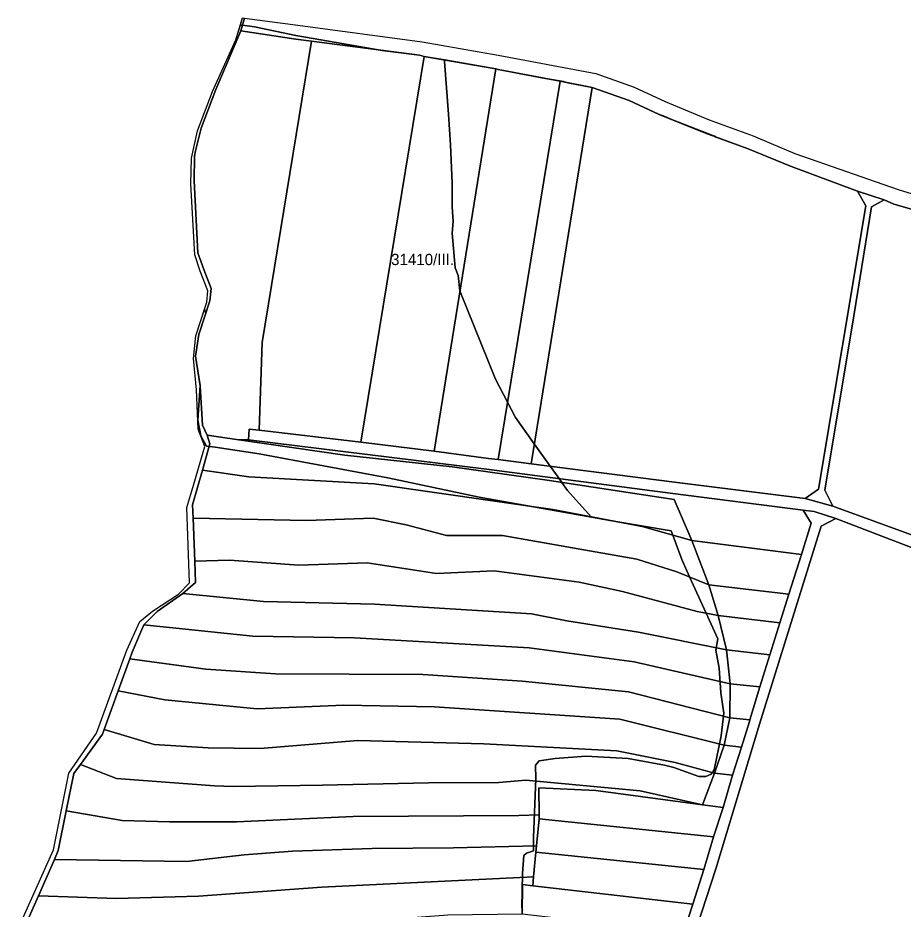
# Model space of a CAD drawing. Extents: x -541351 to -537540, y -1162694 to -1159725.
# Drawn here: x -540770.9 to -540378.9, y -1160119.8 to -1159725 of the extents above; entities that cross this region are included whole.
import ezdxf

# ---------------------------------------------------------------- set-up
doc = ezdxf.new("R2010")
doc.units = 0
for name, color, linetype in [('95560013', 7, 'Continuous'), ('95590013', 7, 'Continuous'), ('95610013', 7, 'Continuous'), ('95620013', 7, 'Continuous'), ('95630013', 7, 'Continuous'), ('95640013', 7, 'Continuous'), ('95660013', 7, 'Continuous')]:
    doc.layers.add(name, color=color, linetype=linetype)

msp = doc.modelspace()

# ---------------------------------------------------------------- linework, layer by layer
at = {"layer": '95560013'}
for points in [[(-540687.01, -1159909.85), (-540689.14, -1159905.33), (-540690.2, -1159888.02), (-540692.23, -1159874.8), (-540690.71, -1159865.31), (-540685.82, -1159850.31), (-540685.23, -1159844.82), (-540688.53, -1159836.42), (-540691.19, -1159829.1), (-540692.84, -1159797.23), (-540692.6, -1159786.19), (-540692.25, -1159783.95), (-540689.66, -1159773.88), (-540683.29, -1159756.73), (-540672.18, -1159730.75), (-540647.86, -1159734.45), (-540640.92, -1159735.38), (-540662.69, -1159868.81), (-540664.02, -1159907.64), (-540668.5, -1159907.14), (-540668.76, -1159911.89), (-540672.98, -1159911.96)], [(-540662.69, -1159868.81), (-540640.92, -1159735.38), (-540593.02, -1159741.59), (-540590.97, -1159742.06), (-540618.99, -1159912.95), (-540664.02, -1159907.64)], [(-540559.26, -1159747.62), (-540586.55, -1159916.94), (-540618.99, -1159912.95), (-540590.97, -1159742.06)], [(-540558.18, -1159920.55), (-540562.46, -1159920.09), (-540586.55, -1159916.94), (-540559.26, -1159747.62), (-540558.18, -1159747.82), (-540530.77, -1159753.07)], [(-540558.18, -1159920.55), (-540530.77, -1159753.07), (-540516.55, -1159755.86), (-540543.65, -1159922.47)], [(-540500.27, -1159761.58), (-540486.88, -1159767.77), (-540466.37, -1159776.14), (-540447.5, -1159783.05), (-540428.8, -1159790.68), (-540399.07, -1159801.69), (-540395.39, -1159808.26), (-540416.42, -1159933.74), (-540422.33, -1159937.95), (-540481.31, -1159930.52), (-540543.65, -1159922.47), (-540516.55, -1159755.86)], [(-540392.94, -1159808.75), (-540387.33, -1159805.56), (-540383.07, -1159807.44), (-540355.38, -1159815.32), (-540315.69, -1159826.05), (-540281.01, -1159835.88), (-540330.36, -1159970.74), (-540352.96, -1159962.05), (-540409.96, -1159941.32), (-540413.54, -1159934.22), (-540400.75, -1159856.93)], [(-540356.83, -1160306.42), (-540508.48, -1160249.81), (-540502.49, -1160230.24), (-540493.25, -1160200.09), (-540483.27, -1160166.95), (-540480.24, -1160158.64), (-540461.87, -1160101.94), (-540442.45, -1160037.81), (-540415.15, -1159950.06), (-540408.75, -1159946.72), (-540359.07, -1159965.85), (-540332.08, -1159975.44), (-540333.53, -1159979.4), (-540310.02, -1160032.13), (-540317.01, -1160072.74), (-540332.5, -1160163.53), (-540349.68, -1160266.25)]]:
    msp.add_lwpolyline(points, close=True, dxfattribs=at)
at = {"layer": '95590013'}
for points in [[(-540672.98, -1159911.96), (-540668.76, -1159911.89), (-540563.34, -1159924.9), (-540480.83, -1159935.64), (-540423.17, -1159943.05), (-540419.69, -1159948.79), (-540423.93, -1159962.65), (-540472.52, -1159956.54), (-540480.23, -1159938.25), (-540536.53, -1159929.78), (-540578.61, -1159923.89), (-540626.15, -1159918.63)], [(-540429.55, -1159980.28), (-540464.95, -1159976.07), (-540472.52, -1159956.54), (-540423.93, -1159962.65)]]:
    msp.add_lwpolyline(points, close=True, dxfattribs=at)
at = {"layer": '95610013'}
for points in [[(-540416.42, -1159933.74), (-540395.39, -1159808.26), (-540399.07, -1159801.69), (-540387.33, -1159805.56), (-540392.94, -1159808.75), (-540400.75, -1159856.93), (-540413.54, -1159934.22), (-540409.96, -1159941.32), (-540422.33, -1159937.95)], [(-540467.2, -1160102.19), (-540541.49, -1160094.53), (-540541.2, -1160091.66), (-540540.01, -1160079.71), (-540462.81, -1160087.74), (-540466.74, -1160100.71)], [(-540542.51, -1160105.39), (-540541.49, -1160094.53), (-540467.2, -1160102.19), (-540472.02, -1160117.6), (-540542.89, -1160109.37)], [(-540472.02, -1160117.6), (-540476.19, -1160130.2), (-540547.6, -1160121.95), (-540547.45, -1160108.79), (-540542.89, -1160109.37)]]:
    msp.add_lwpolyline(points, close=True, dxfattribs=at)
at = {"layer": '95620013'}
for points in [[(-540536.53, -1159929.78), (-540480.23, -1159938.25), (-540472.52, -1159956.54), (-540494.39, -1159950.23), (-540534.02, -1159942.82), (-540613.05, -1159931.36), (-540668.68, -1159928.25), (-540689.1, -1159925.28), (-540685.86, -1159913.66), (-540687.01, -1159909.85), (-540672.98, -1159911.96), (-540626.15, -1159918.63), (-540578.61, -1159923.89)], [(-540693.27, -1159946.58), (-540693.48, -1159940.71), (-540689.1, -1159925.28), (-540668.68, -1159928.25), (-540613.05, -1159931.36), (-540534.02, -1159942.82), (-540494.39, -1159950.23), (-540472.52, -1159956.54), (-540464.95, -1159976.07), (-540479.17, -1159970.29), (-540496.78, -1159964.81), (-540556.23, -1159954.29), (-540581.06, -1159954.29), (-540598.9, -1159949.56), (-540613.53, -1159946.65), (-540643.03, -1159947.58)], [(-540616.21, -1159966.36), (-540646.47, -1159967.48), (-540677.1, -1159965.24), (-540692.59, -1159965.67), (-540693.27, -1159946.58), (-540643.03, -1159947.58), (-540613.53, -1159946.65), (-540598.9, -1159949.56), (-540581.06, -1159954.29), (-540556.23, -1159954.29), (-540496.78, -1159964.81), (-540479.17, -1159970.29), (-540464.95, -1159976.07), (-540460.86, -1159989.73), (-540470.08, -1159987.93), (-540503.12, -1159979.1), (-540522.36, -1159974.98), (-540559.91, -1159969.94), (-540585.58, -1159971.03)], [(-540496.05, -1159997.14), (-540527.86, -1159992), (-540543.42, -1159988.94), (-540612.9, -1159984.64), (-540662.17, -1159983.52), (-540697.84, -1159979.97), (-540692.26, -1159975.02), (-540692.59, -1159965.67), (-540677.1, -1159965.24), (-540646.47, -1159967.48), (-540616.21, -1159966.36), (-540585.58, -1159971.03), (-540559.91, -1159969.94), (-540522.36, -1159974.98), (-540503.12, -1159979.1), (-540470.08, -1159987.93), (-540460.86, -1159989.73), (-540457.12, -1160004.92)], [(-540433.56, -1159992.96), (-540460.86, -1159989.73), (-540464.95, -1159976.07), (-540429.55, -1159980.28)], [(-540697.84, -1159979.97), (-540662.17, -1159983.52), (-540612.9, -1159984.64), (-540543.42, -1159988.94), (-540527.86, -1159992), (-540496.05, -1159997.14), (-540457.12, -1160004.92), (-540455.54, -1160019.94), (-540497.92, -1160010.22), (-540544.54, -1160004.08), (-540621.87, -1159999.59), (-540666.84, -1159998.85), (-540715.03, -1159993.81), (-540709.25, -1159987.89)], [(-540437.87, -1160007.17), (-540457.12, -1160004.92), (-540460.86, -1159989.73), (-540433.56, -1159992.96)], [(-540715.03, -1159993.81), (-540666.84, -1159998.85), (-540621.87, -1159999.59), (-540544.54, -1160004.08), (-540497.92, -1160010.22), (-540455.54, -1160019.94), (-540455.66, -1160035.04), (-540500.53, -1160023.5), (-540547.53, -1160018.85), (-540591.61, -1160015.86), (-540656.75, -1160015.49), (-540687.66, -1160013.44), (-540721.28, -1160008.95), (-540720.26, -1160005.89)], [(-540437.87, -1160007.17), (-540442.31, -1160021.34), (-540455.54, -1160019.94), (-540457.12, -1160004.92)], [(-540705.82, -1160027.02), (-540726.43, -1160023.14), (-540721.28, -1160008.95), (-540687.66, -1160013.44), (-540656.75, -1160015.49), (-540591.61, -1160015.86), (-540547.53, -1160018.85), (-540500.53, -1160023.5), (-540455.66, -1160035.04), (-540458.18, -1160047.18), (-540504.34, -1160035.64), (-540586.36, -1160030.14), (-540626.52, -1160029.41), (-540664.93, -1160031.05)], [(-540446.8, -1160035.97), (-540455.66, -1160035.04), (-540455.54, -1160019.94), (-540442.31, -1160021.34)], [(-540626.52, -1160029.41), (-540586.36, -1160030.14), (-540504.34, -1160035.64), (-540458.18, -1160047.18), (-540462.48, -1160059.55), (-540479.77, -1160054.82), (-540505.72, -1160049.59), (-540564.54, -1160046.47), (-540620.29, -1160045), (-540663.56, -1160048.68), (-540686.57, -1160048.3), (-540710.59, -1160046.84), (-540732.64, -1160040.22), (-540726.43, -1160023.14), (-540705.82, -1160027.02), (-540664.93, -1160031.05)], [(-540450.44, -1160047.98), (-540458.18, -1160047.18), (-540455.66, -1160035.04), (-540446.8, -1160035.97), (-540446.94, -1160036.71)], [(-540727.16, -1160061.87), (-540743.15, -1160055.68), (-540733.36, -1160042.21), (-540732.64, -1160040.22), (-540710.59, -1160046.84), (-540686.57, -1160048.3), (-540663.56, -1160048.68), (-540620.29, -1160045), (-540564.54, -1160046.47), (-540505.72, -1160049.59), (-540479.77, -1160054.82), (-540462.48, -1160059.55), (-540467.72, -1160073.61), (-540495.27, -1160067.42), (-540545.9, -1160062.63), (-540557.89, -1160063.64), (-540589.13, -1160063.89), (-540635.98, -1160064.9), (-540675.53, -1160065.4), (-540683.84, -1160065.15)], [(-540458.18, -1160047.18), (-540450.44, -1160047.98), (-540454.46, -1160060.44), (-540462.48, -1160059.55)], [(-540746.06, -1160059.68), (-540743.15, -1160055.68), (-540727.16, -1160061.87), (-540683.84, -1160065.15), (-540675.53, -1160065.4), (-540635.98, -1160064.9), (-540589.13, -1160063.89), (-540557.89, -1160063.64), (-540545.9, -1160062.63), (-540495.27, -1160067.42), (-540467.72, -1160073.61), (-540514.98, -1160067.2), (-540540.15, -1160065.96), (-540540.03, -1160077.93), (-540549.08, -1160078.26), (-540622.38, -1160078.76), (-540674.01, -1160081.03), (-540703.74, -1160081.03), (-540724.64, -1160080.52), (-540749.42, -1160076.24)], [(-540462.48, -1160059.55), (-540454.46, -1160060.44), (-540458.62, -1160074.7), (-540467.72, -1160073.61)], [(-540540.15, -1160065.96), (-540514.98, -1160067.2), (-540467.72, -1160073.61), (-540458.62, -1160074.7), (-540462.81, -1160087.74), (-540540.01, -1160079.71), (-540540.03, -1160077.93)], [(-540696.18, -1160098.67), (-540754.72, -1160097.77), (-540752.97, -1160093.75), (-540749.42, -1160076.24), (-540724.64, -1160080.52), (-540703.74, -1160081.03), (-540674.01, -1160081.03), (-540622.38, -1160078.76), (-540549.08, -1160078.26), (-540540.03, -1160077.93), (-540540.01, -1160079.71), (-540541.2, -1160091.66), (-540578.04, -1160092.62), (-540614.06, -1160092.87), (-540649.33, -1160094.14), (-540670.74, -1160095.65)], [(-540761.74, -1160113.85), (-540754.72, -1160097.77), (-540696.18, -1160098.67), (-540670.74, -1160095.65), (-540649.33, -1160094.14), (-540614.06, -1160092.87), (-540578.04, -1160092.62), (-540541.2, -1160091.66), (-540541.49, -1160094.53), (-540542.51, -1160105.39), (-540636.23, -1160110.02), (-540690.89, -1160114.05), (-540727.16, -1160115.06)], [(-540580.56, -1160122.37), (-540627.16, -1160125.9), (-540672.5, -1160131.19), (-540690.64, -1160131.86), (-540706.51, -1160132.45), (-540756.13, -1160129.17), (-540770.89, -1160129.16), (-540766.4, -1160124.54), (-540761.74, -1160113.85), (-540727.16, -1160115.06), (-540690.89, -1160114.05), (-540636.23, -1160110.02), (-540542.51, -1160105.39), (-540542.89, -1160109.37), (-540547.45, -1160108.79), (-540547.6, -1160121.95)]]:
    msp.add_lwpolyline(points, close=True, dxfattribs=at)
at = {"layer": '95630013'}
msp.add_lwpolyline([(-540768.54, -1160123.44), (-540755.16, -1160093.5), (-540748.37, -1160059.49), (-540736.1, -1160041.86), (-540722.61, -1160005.06), (-540716.88, -1159992.34), (-540711.26, -1159987.75), (-540699.68, -1159980.19), (-540694.83, -1159975.26), (-540696, -1159941.92), (-540692.98, -1159931.51), (-540688.11, -1159914.9), (-540691.02, -1159907.19), (-540691.85, -1159889.7), (-540693.14, -1159875.87), (-540692.08, -1159865.82), (-540687.15, -1159850.98), (-540686.73, -1159845.84), (-540690.13, -1159837.23), (-540692.59, -1159829.95), (-540694.34, -1159798.44), (-540693.97, -1159787.19), (-540691.38, -1159775), (-540684.74, -1159757.57), (-540674.38, -1159734.7), (-540671.39, -1159724.98), (-540670.49, -1159725.12), (-540672.18, -1159730.75), (-540683.29, -1159756.73), (-540689.66, -1159773.88), (-540692.25, -1159783.95), (-540692.6, -1159786.19), (-540692.84, -1159797.23), (-540691.19, -1159829.1), (-540688.53, -1159836.42), (-540685.23, -1159844.82), (-540685.82, -1159850.31), (-540690.71, -1159865.31), (-540692.23, -1159874.8), (-540690.2, -1159888.02), (-540689.14, -1159905.33), (-540687.01, -1159909.85), (-540685.86, -1159913.66), (-540689.1, -1159925.28), (-540693.48, -1159940.71), (-540693.27, -1159946.58), (-540692.59, -1159965.67), (-540692.26, -1159975.02), (-540697.84, -1159979.97), (-540709.25, -1159987.89), (-540715.03, -1159993.81), (-540720.26, -1160005.89), (-540721.28, -1160008.95), (-540726.43, -1160023.14), (-540732.64, -1160040.22), (-540733.36, -1160042.21), (-540743.15, -1160055.68), (-540746.06, -1160059.68), (-540749.42, -1160076.24), (-540752.97, -1160093.75), (-540754.72, -1160097.77), (-540761.74, -1160113.85), (-540766.4, -1160124.54)], dxfattribs=at)
at = {"layer": '95640013'}
for points in [[(-540355.38, -1159815.32), (-540383.07, -1159807.44), (-540387.33, -1159805.56), (-540399.07, -1159801.69), (-540428.8, -1159790.68), (-540447.5, -1159783.05), (-540466.37, -1159776.14), (-540486.88, -1159767.77), (-540500.27, -1159761.58), (-540516.55, -1159755.86), (-540530.77, -1159753.07), (-540558.18, -1159747.82), (-540559.26, -1159747.62), (-540590.97, -1159742.06), (-540593.02, -1159741.59), (-540640.92, -1159735.38), (-540647.86, -1159734.45), (-540672.18, -1159730.75), (-540670.49, -1159725.12), (-540646.88, -1159728.27), (-540591.85, -1159735.55), (-540558.28, -1159741.53), (-540514.9, -1159749.61), (-540497.97, -1159755.73), (-540484.31, -1159762), (-540464.74, -1159770.11), (-540445.32, -1159777.26), (-540437.31, -1159780.66), (-540426.9, -1159785.09), (-540381.17, -1159801.03), (-540353.86, -1159809.47)], [(-540476.19, -1160130.2), (-540472.02, -1160117.6), (-540467.2, -1160102.19), (-540466.74, -1160100.71), (-540462.81, -1160087.74), (-540458.62, -1160074.7), (-540454.46, -1160060.44), (-540450.44, -1160047.98), (-540446.94, -1160036.71), (-540446.8, -1160035.97), (-540442.31, -1160021.34), (-540437.87, -1160007.17), (-540433.56, -1159992.96), (-540429.55, -1159980.28), (-540423.93, -1159962.65), (-540419.69, -1159948.79), (-540423.17, -1159943.05), (-540418.31, -1159943.64), (-540408.75, -1159946.72), (-540415.15, -1159950.06), (-540442.45, -1160037.81), (-540461.87, -1160101.94), (-540480.24, -1160158.64)]]:
    msp.add_lwpolyline(points, dxfattribs=at)
msp.add_lwpolyline([(-540422.33, -1159937.95), (-540409.96, -1159941.32), (-540352.96, -1159962.05), (-540330.36, -1159970.74), (-540332.08, -1159975.44), (-540359.07, -1159965.85), (-540408.75, -1159946.72), (-540418.31, -1159943.64), (-540423.17, -1159943.05), (-540480.83, -1159935.64), (-540563.34, -1159924.9), (-540668.76, -1159911.89), (-540668.5, -1159907.14), (-540664.02, -1159907.64), (-540618.99, -1159912.95), (-540586.55, -1159916.94), (-540562.46, -1159920.09), (-540558.18, -1159920.55), (-540543.65, -1159922.47), (-540481.31, -1159930.52)], close=True, dxfattribs=at)
at = {"layer": '95660013'}
for points in [[(-540355.38, -1159815.32), (-540383.07, -1159807.44), (-540387.33, -1159805.56), (-540399.07, -1159801.69), (-540428.8, -1159790.68), (-540447.5, -1159783.05), (-540461.75, -1159777.83), (-540462.47, -1159777.42), (-540481, -1159770.17), (-540484.48, -1159768.75), (-540487.23, -1159767.6), (-540500.27, -1159761.58), (-540516.55, -1159755.86), (-540527.29, -1159753.75), (-540529.21, -1159753.19), (-540537.28, -1159751.82), (-540558.18, -1159747.82), (-540559.26, -1159747.62), (-540581.98, -1159743.64), (-540590.97, -1159742.06), (-540593.02, -1159741.59), (-540609.61, -1159739.44), (-540647.82, -1159732.78), (-540666.1, -1159728.96), (-540671.44, -1159728.3), (-540672.37, -1159728.18), (-540671.39, -1159724.98), (-540670.49, -1159725.12), (-540646.88, -1159728.27), (-540591.85, -1159735.55), (-540558.28, -1159741.53), (-540514.9, -1159749.61), (-540497.97, -1159755.73), (-540484.31, -1159762), (-540464.74, -1159770.11), (-540445.32, -1159777.26), (-540437.31, -1159780.66), (-540426.9, -1159785.09), (-540381.17, -1159801.03), (-540353.86, -1159809.47)], [(-540547.44, -1160119.89), (-540547.69, -1160119), (-540547.5, -1160104), (-540546.81, -1160096), (-540545.62, -1160095), (-540542.62, -1160094), (-540542.62, -1160088), (-540541.5, -1160062), (-540541.62, -1160056), (-540540.12, -1160054), (-540533, -1160053), (-540519.37, -1160052), (-540500.62, -1160053), (-540484.5, -1160056), (-540480.5, -1160057), (-540469.31, -1160061), (-540466.31, -1160061), (-540463.87, -1160060), (-540462.62, -1160058), (-540459.5, -1160043), (-540458.31, -1160033), (-540459.62, -1160024), (-540460.37, -1160013), (-540461.81, -1160005), (-540461.01, -1160000), (-540466.13, -1159988.7), (-540473.42, -1159972.63), (-540476.92, -1159964.89), (-540480.87, -1159954.13), (-540481.6, -1159952.14), (-540507.85, -1159947.71), (-540516.89, -1159946.19), (-540517.06, -1159945.99), (-540527.51, -1159934.29), (-540530.02, -1159930.76), (-540531.21, -1159929.08), (-540535.13, -1159923.57), (-540542.21, -1159913.6), (-540550.47, -1159901.98), (-540554.03, -1159895.2), (-540559.4, -1159884.97), (-540575.11, -1159845.89), (-540575.98, -1159839.06), (-540577.25, -1159835.66), (-540578.53, -1159820.36), (-540578.1, -1159815.25), (-540578.38, -1159810.85), (-540578.53, -1159808.45), (-540578.53, -1159798.25), (-540579.38, -1159781.25), (-540580.23, -1159767.64), (-540581.93, -1159744.26), (-540581.98, -1159743.64), (-540559.26, -1159747.62), (-540558.18, -1159747.82), (-540537.28, -1159751.82), (-540529.21, -1159753.19), (-540527.29, -1159753.75), (-540516.55, -1159755.86), (-540500.27, -1159761.58), (-540487.23, -1159767.6), (-540484.48, -1159768.75), (-540481, -1159770.17), (-540462.47, -1159777.42), (-540461.75, -1159777.83), (-540447.5, -1159783.05), (-540428.8, -1159790.68), (-540399.07, -1159801.69), (-540387.33, -1159805.56), (-540383.07, -1159807.44), (-540355.38, -1159815.32)], [(-540768.54, -1160123.44), (-540755.16, -1160093.5), (-540748.37, -1160059.49), (-540736.1, -1160041.86), (-540722.61, -1160005.06), (-540716.88, -1159992.34), (-540711.26, -1159987.75), (-540699.68, -1159980.19), (-540694.83, -1159975.26), (-540696, -1159941.92), (-540692.98, -1159931.51), (-540688.11, -1159914.9), (-540691.02, -1159907.19), (-540691.85, -1159889.7), (-540693.14, -1159875.87), (-540692.08, -1159865.82), (-540688.17, -1159854.05), (-540687.6, -1159855.77), (-540690.71, -1159865.31), (-540692.23, -1159874.8), (-540690.22, -1159887.87), (-540691.18, -1159903.25), (-540689.91, -1159910.05), (-540687.36, -1159914.73), (-540686.19, -1159914.86), (-540685.86, -1159914.9), (-540683.53, -1159915.16), (-540663.98, -1159918.13), (-540607.01, -1159928.76), (-540566.62, -1159937.26), (-540542.55, -1159941.58), (-540516.89, -1159946.19), (-540507.85, -1159947.71), (-540481.6, -1159952.14), (-540480.87, -1159954.13), (-540476.92, -1159964.89), (-540473.42, -1159972.63), (-540466.13, -1159988.7), (-540461.01, -1160000), (-540461.81, -1160005), (-540460.37, -1160013), (-540459.62, -1160024), (-540458.31, -1160033), (-540459.5, -1160043), (-540462.62, -1160058), (-540463.87, -1160060), (-540466.31, -1160061), (-540469.31, -1160061), (-540480.5, -1160057), (-540484.5, -1160056), (-540500.62, -1160053), (-540519.37, -1160052), (-540533, -1160053), (-540540.12, -1160054), (-540541.62, -1160056), (-540541.5, -1160062), (-540542.62, -1160088), (-540542.62, -1160094), (-540545.62, -1160095), (-540546.81, -1160096), (-540547.5, -1160104), (-540547.69, -1160119), (-540547.44, -1160119.89)]]:
    msp.add_lwpolyline(points, dxfattribs=at)
msp.add_lwpolyline([(-540674.38, -1159734.7), (-540672.37, -1159728.18), (-540671.44, -1159728.3), (-540666.1, -1159728.96), (-540647.82, -1159732.78), (-540609.61, -1159739.44), (-540593.02, -1159741.59), (-540590.97, -1159742.06), (-540581.98, -1159743.64), (-540581.93, -1159744.26), (-540580.23, -1159767.64), (-540579.38, -1159781.25), (-540578.53, -1159798.25), (-540578.53, -1159808.45), (-540578.38, -1159810.85), (-540578.1, -1159815.25), (-540578.53, -1159820.36), (-540577.25, -1159835.66), (-540575.98, -1159839.06), (-540575.11, -1159845.89), (-540559.4, -1159884.97), (-540554.03, -1159895.2), (-540550.47, -1159901.98), (-540542.21, -1159913.6), (-540535.13, -1159923.57), (-540531.21, -1159929.08), (-540530.02, -1159930.76), (-540527.51, -1159934.29), (-540517.06, -1159945.99), (-540516.89, -1159946.19), (-540542.55, -1159941.58), (-540566.62, -1159937.26), (-540607.01, -1159928.76), (-540663.98, -1159918.13), (-540683.53, -1159915.16), (-540685.86, -1159914.9), (-540686.19, -1159914.86), (-540687.36, -1159914.73), (-540689.91, -1159910.05), (-540691.18, -1159903.25), (-540690.22, -1159887.87), (-540692.23, -1159874.8), (-540690.71, -1159865.31), (-540687.6, -1159855.77), (-540688.17, -1159854.05), (-540687.15, -1159850.98), (-540686.73, -1159845.84), (-540690.13, -1159837.23), (-540692.59, -1159829.95), (-540694.34, -1159798.44), (-540693.97, -1159787.19), (-540691.38, -1159775), (-540684.74, -1159757.57)], close=True, dxfattribs=at)

# ---------------------------------------------------------------- texts
msp.add_text('31410/III.', height=5, rotation=360, dxfattribs=at).set_placement((-540605.61, -1159834.51))

doc.saveas('drawing.dxf')
